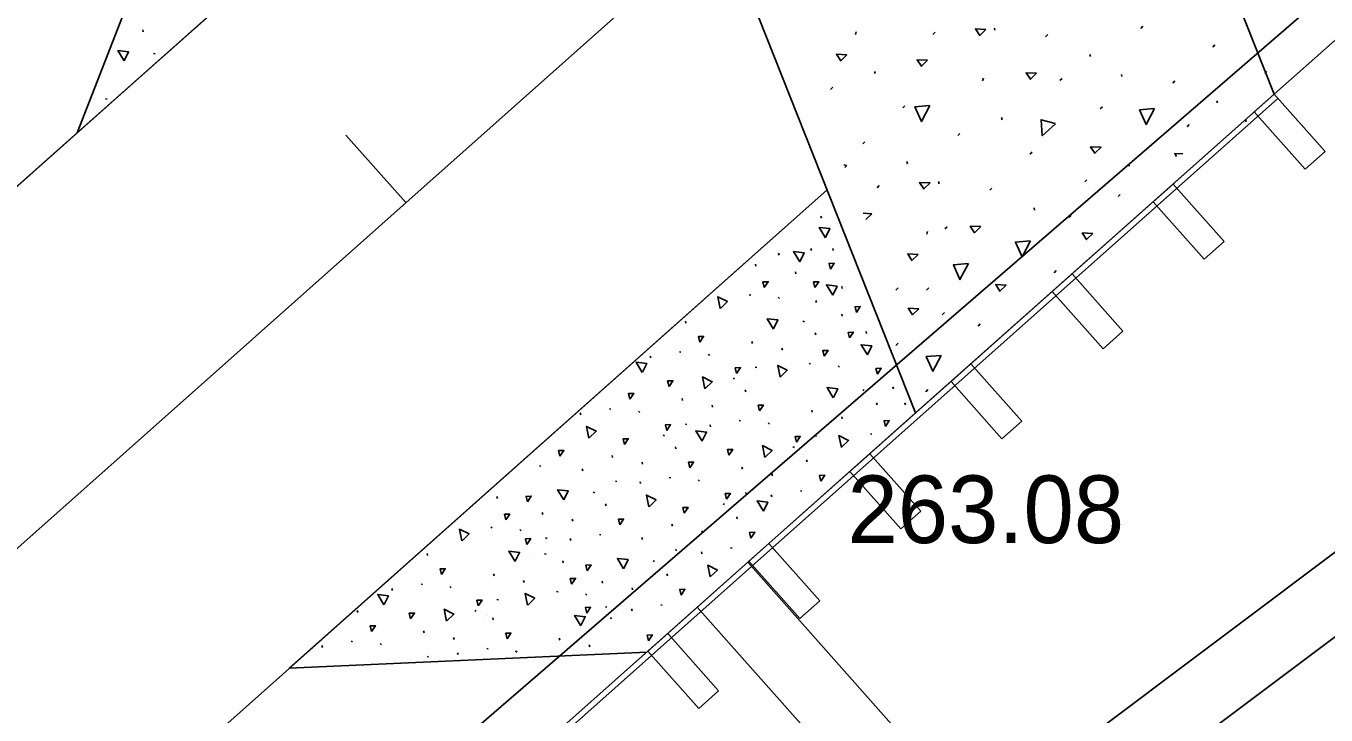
# Model space of a CAD drawing. Extents: x 49683 to 58852, y 49525 to 54803.
# Drawn here: x 55243.3 to 55301, y 53014 to 53044.6 of the extents above; entities that cross this region are included whole.
import ezdxf

# ---------------------------------------------------------------- set-up
doc = ezdxf.new("R2010")
doc.units = 0
for name, color, linetype in [('Level 11', 7, 'Continuous'), ('Level 13', 7, 'Continuous'), ('Level 15', 7, 'Continuous'), ('Level 18', 7, 'Continuous'), ('Level 19', 7, 'Continuous'), ('Level 20', 7, 'Continuous'), ('Level 27', 7, 'Continuous'), ('Level 32', 7, 'Continuous'), ('Level 8', 7, 'Continuous')]:
    doc.layers.add(name, color=color, linetype=linetype)

msp = doc.modelspace()

# ---------------------------------------------------------------- linework, layer by layer
at = {"layer": 'Level 11'}
msp.add_line((55223.521, 52979.087), (55416.975, 53146.156), dxfattribs=at)
at = {"layer": 'Level 13'}
msp.add_line((55279.532, 53069.998), (53969.027, 51905.114), dxfattribs=at)
at = {"layer": 'Level 15'}
for p, q in [((55298.696, 53041.543), (55388.385, 53121.267)), ((55298.696, 53041.543), (55281.433, 53085.069)), ((55282.788, 53027.404), (55265.526, 53070.929)), ((55245.587, 53039.827), (55269.449, 53061.037)), ((55253.595, 53060.324), (55245.587, 53039.827)), ((55286.304, 53044.375), (55286.28, 53044.472)), ((55292.866, 53044.556), (55292.771, 53044.457)), ((55280.123, 53044.188), (55280.153, 53044.31)), ((55283.648, 53044.294), (55283.553, 53044.195)), ((55288.65, 53044.186), (55288.555, 53044.088)), ((55290.541, 53043.209), (55290.517, 53043.306)), ((55296.066, 53043.731), (55295.971, 53043.633)), ((55280.986, 53042.457), (55280.962, 53042.554)), ((55285.761, 53042.136), (55285.791, 53042.258)), ((55289.286, 53042.242), (55289.191, 53042.143)), ((55291.942, 53042.323), (55291.918, 53042.42)), ((55294.288, 53042.134), (55294.193, 53042.035)), ((55298.37, 53042.553), (55298.275, 53042.454)), ((55279.113, 53041.854), (55279.018, 53041.756)), ((55282.788, 53027.404), (55298.696, 53041.543)), ((55282.312, 53041.029), (55282.217, 53040.931)), ((55291.073, 53040.986), (55290.978, 53040.887)), ((55296.179, 53041.156), (55296.156, 53041.254)), ((55286.624, 53040.405), (55286.6, 53040.502)), ((55297.446, 53040.32), (55297.422, 53040.417)), ((55284.751, 53039.802), (55284.656, 53039.704)), ((55294.924, 53040.19), (55294.829, 53040.091)), ((55280.535, 53039.432), (55280.44, 53039.334)), ((55287.95, 53038.977), (55287.855, 53038.879)), ((55282.426, 53038.455), (55282.402, 53038.552)), ((55292.262, 53038.353), (55292.239, 53038.45)), ((55281.171, 53037.488), (55281.076, 53037.389)), ((55283.826, 53037.569), (55283.803, 53037.667)), ((55290.389, 53037.75), (55290.294, 53037.652)), ((55255.003, 53016.086), (55278.865, 53037.296)), ((55286.173, 53037.38), (55286.078, 53037.282)), ((55291.86, 53037.1), (55291.765, 53037.001)), ((55288.064, 53036.403), (55288.04, 53036.5)), ((55289.689, 53036.168), (55289.594, 53036.07)), ((55283.284, 53035.33), (55283.314, 53035.452)), ((55284.182, 53035.664), (55284.087, 53035.565)), ((55289.029, 53033.723), (55288.934, 53033.625)), ((55282.01, 53032.947), (55281.915, 53032.849)), ((55283.367, 53032.947), (55283.272, 53032.849)), ((55284.065, 53031.86), (55283.97, 53031.762)), ((55285.655, 53031.356), (55285.56, 53031.257)), ((55282.01, 53030.502), (55281.915, 53030.404)), ((55283.329, 53028.445), (55283.234, 53028.347)), ((55270.857, 53016.799), (55282.788, 53027.404)), ((55275.342, 53020.785), (55285.8, 53009.019)), ((55273.099, 53018.792), (55283.337, 53007.275)), ((55255.003, 53016.086), (55270.857, 53016.799))]:
    msp.add_line(p, q, dxfattribs=at)
for points in [[(55285.907, 53044.416), (55285.632, 53044.147), (55285.443, 53044.438), (55285.907, 53044.416)], [(55279.74, 53043.294), (55279.465, 53043.025), (55279.276, 53043.316), (55279.74, 53043.294)], [(55283.318, 53043.048), (55283.043, 53042.778), (55282.854, 53043.069), (55283.318, 53043.048)], [(55288.154, 53042.473), (55287.879, 53042.204), (55287.689, 53042.494), (55288.154, 53042.473)], [(55283.423, 53041.038), (55283.048, 53040.33), (55282.757, 53040.982), (55283.409, 53041.038)], [(55293.387, 53040.902), (55293.012, 53040.194), (55292.721, 53040.846), (55293.373, 53040.902)], [(55288.995, 53040.234), (55288.401, 53039.698), (55288.35, 53040.41), (55288.982, 53040.239)], [(55291.017, 53039.19), (55290.742, 53038.921), (55290.552, 53039.212), (55291.017, 53039.19)], [(55294.364, 53038.781), (55294.279, 53038.911), (55294.648, 53038.894)], [(55279.609, 53038.409), (55279.726, 53038.378)], [(55279.739, 53038.373), (55279.654, 53038.297)], [(55283.43, 53037.611), (55283.155, 53037.342), (55282.966, 53037.632), (55283.43, 53037.611)], [(55280.462, 53036.259), (55280.841, 53036.242)], [(55280.841, 53036.242), (55280.573, 53035.979)], [(55285.677, 53035.667), (55285.402, 53035.398), (55285.212, 53035.688), (55285.677, 53035.667)], [(55290.644, 53035.364), (55290.369, 53035.095), (55290.179, 53035.386), (55290.644, 53035.364)], [(55287.881, 53035.035), (55287.507, 53034.327), (55287.215, 53034.98), (55287.868, 53035.035)], [(55282.901, 53034.436), (55282.626, 53034.167), (55282.437, 53034.458), (55282.901, 53034.436)], [(55285.128, 53034.026), (55284.753, 53033.318), (55284.462, 53033.971), (55285.114, 53034.026)], [(55286.805, 53033.075), (55286.53, 53032.806), (55286.34, 53033.096), (55286.805, 53033.075)], [(55282.927, 53032.027), (55282.652, 53031.758), (55282.462, 53032.048), (55282.927, 53032.027)], [(55283.927, 53029.96), (55283.552, 53029.252), (55283.261, 53029.904), (55283.913, 53029.96)]]:
    msp.add_lwpolyline(points, dxfattribs=at)
at = {"layer": 'Level 18'}
for p, q in [((55284.924, 53008.881), (55312.522, 53029.585)), ((55286.724, 53006.481), (55314.322, 53027.185))]:
    msp.add_line(p, q, dxfattribs=at)
at = {"layer": 'Level 19'}
for p, q in [((54181.768, 52078.16), (56150.851, 53828.445)), ((55260.168, 53036.732), (55257.51, 53039.721))]:
    msp.add_line(p, q, dxfattribs=at)
at = {"layer": 'Level 20'}
for p, q in [((54173.795, 52087.129), (55269.449, 53061.037)), ((54189.74, 52069.191), (55278.865, 53037.296))]:
    msp.add_line(p, q, dxfattribs=at)
at = {"layer": 'Level 27'}
for p, q in [((55275.339, 53020.782), (55298.696, 53041.543)), ((55297.812, 53040.758), (55298.696, 53041.543)), ((55298.696, 53041.543), (55300.954, 53039.002)), ((55275.505, 53020.595), (55298.862, 53041.357)), ((55300.07, 53038.217), (55297.812, 53040.758)), ((55300.954, 53039.002), (55300.07, 53038.217)), ((55293.327, 53036.772), (55294.211, 53037.557)), ((55294.211, 53037.557), (55296.469, 53035.016)), ((55295.586, 53034.231), (55293.327, 53036.772)), ((55296.469, 53035.016), (55295.586, 53034.231)), ((55288.843, 53032.786), (55289.727, 53033.571)), ((55289.727, 53033.571), (55291.985, 53031.03)), ((55291.101, 53030.244), (55288.843, 53032.786)), ((55291.985, 53031.03), (55291.101, 53030.244)), ((55284.359, 53028.8), (55285.242, 53029.585)), ((55285.242, 53029.585), (55287.501, 53027.043)), ((55286.617, 53026.258), (55284.359, 53028.8)), ((55287.501, 53027.043), (55286.617, 53026.258)), ((55279.874, 53024.814), (55280.758, 53025.599)), ((55280.758, 53025.599), (55283.016, 53023.057)), ((55282.133, 53022.272), (55279.874, 53024.814)), ((55283.016, 53023.057), (55282.133, 53022.272)), ((55275.39, 53020.827), (55276.273, 53021.613)), ((55276.273, 53021.613), (55278.532, 53019.071)), ((55275.339, 53020.782), (55265.996, 53012.478)), ((55277.648, 53018.286), (55275.39, 53020.827)), ((55275.505, 53020.595), (55266.162, 53012.291)), ((55278.532, 53019.071), (55277.648, 53018.286)), ((55270.905, 53016.841), (55271.789, 53017.626)), ((55271.789, 53017.626), (55274.047, 53015.085)), ((55273.164, 53014.3), (55270.905, 53016.841)), ((55274.047, 53015.085), (55273.164, 53014.3))]:
    msp.add_line(p, q, dxfattribs=at)
at = {"layer": 'Level 8'}
for p, q in [((55248.526, 53044.303), (55248.503, 53044.391)), ((55248.987, 53043.345), (55249.051, 53043.325)), ((55246.855, 53041.336), (55246.918, 53041.315)), ((55278.61, 53036.046), (55278.586, 53036.134)), ((55278.165, 53034.609), (55278.141, 53034.697)), ((55279.136, 53034.609), (55279.112, 53034.697)), ((55275.701, 53033.92), (55275.677, 53034.008)), ((55276.729, 53034.407), (55276.705, 53034.494)), ((55277.477, 53033.577), (55277.453, 53033.665)), ((55279.534, 53032.929), (55279.51, 53033.017)), ((55275.407, 53032.642), (55275.47, 53032.623)), ((55276.692, 53032.545), (55276.752, 53032.487)), ((55278.387, 53032.302), (55278.364, 53032.389)), ((55279.534, 53031.694), (55279.51, 53031.782)), ((55272.601, 53031.393), (55272.577, 53031.481)), ((55277.789, 53031.47), (55277.853, 53031.45)), ((55275.549, 53030.491), (55275.525, 53030.579)), ((55278.356, 53030.874), (55278.332, 53030.962)), ((55280.612, 53030.925), (55280.588, 53031.013)), ((55271.036, 53029.843), (55271.012, 53029.931)), ((55272.306, 53030.115), (55272.37, 53030.095)), ((55273.592, 53030.018), (55273.651, 53029.959)), ((55276.879, 53030.191), (55276.856, 53030.279)), ((55275.674, 53029.442), (55275.738, 53029.422)), ((55278.061, 53029.596), (55278.125, 53029.577)), ((55279.347, 53029.499), (55279.407, 53029.44)), ((55274.689, 53028.943), (55274.752, 53028.923)), ((55275.124, 53028.618), (55275.124, 53028.618)), ((55275.255, 53028.347), (55275.231, 53028.435)), ((55275.253, 53028.724), (55275.253, 53028.724)), ((55280.444, 53028.424), (55280.508, 53028.404)), ((55281.805, 53028.476), (55281.782, 53028.564)), ((55272.448, 53027.964), (55272.425, 53028.052)), ((55273.779, 53027.664), (55273.755, 53027.752)), ((55281.075, 53027.763), (55281.051, 53027.851)), ((55282.331, 53027.768), (55282.307, 53027.855)), ((55267.935, 53027.316), (55267.911, 53027.404)), ((55269.205, 53027.588), (55269.269, 53027.568)), ((55270.491, 53027.491), (55270.551, 53027.432)), ((55274.961, 53027.069), (55275.024, 53027.049)), ((55278.204, 53027.445), (55278.18, 53027.533)), ((55279.534, 53027.145), (55279.51, 53027.233)), ((55272.573, 53026.915), (55272.637, 53026.895)), ((55273.69, 53026.797), (55273.667, 53026.885)), ((55276.246, 53026.972), (55276.306, 53026.913)), ((55280.781, 53026.485), (55280.844, 53026.466)), ((55271.588, 53026.415), (55271.652, 53026.396)), ((55272.023, 53026.091), (55272.023, 53026.091)), ((55272.155, 53025.82), (55272.131, 53025.908)), ((55272.152, 53026.196), (55272.152, 53026.196)), ((55277.343, 53025.897), (55277.407, 53025.877)), ((55278.329, 53026.396), (55278.392, 53026.376)), ((55269.348, 53025.437), (55269.324, 53025.525)), ((55277.778, 53025.572), (55277.778, 53025.572)), ((55277.908, 53025.677), (55277.908, 53025.677)), ((55277.975, 53025.236), (55277.951, 53025.324)), ((55266.105, 53025.061), (55266.169, 53025.041)), ((55268.019, 53024.842), (55267.994, 53024.93)), ((55270.678, 53025.137), (55270.654, 53025.225)), ((55275.103, 53024.918), (55275.079, 53025.006)), ((55269.473, 53024.388), (55269.537, 53024.368)), ((55270.59, 53024.27), (55270.566, 53024.358)), ((55271.86, 53024.542), (55271.924, 53024.522)), ((55273.146, 53024.445), (55273.205, 53024.386)), ((55276.433, 53024.618), (55276.41, 53024.706)), ((55264.241, 53023.616), (55264.217, 53023.704)), ((55268.488, 53023.888), (55268.551, 53023.869)), ((55269.052, 53023.669), (55269.052, 53023.669)), ((55275.228, 53023.869), (55275.292, 53023.849)), ((55276.41, 53023.686), (55276.386, 53023.774)), ((55277.68, 53023.958), (55277.744, 53023.938)), ((55268.923, 53023.564), (55268.923, 53023.564)), ((55269.054, 53023.293), (55269.03, 53023.381)), ((55274.243, 53023.369), (55274.306, 53023.35)), ((55274.678, 53023.045), (55274.678, 53023.045)), ((55274.807, 53023.15), (55274.807, 53023.15)), ((55266.247, 53022.909), (55266.223, 53022.997)), ((55267.578, 53022.609), (55267.554, 53022.697)), ((55272.003, 53022.39), (55271.979, 53022.478)), ((55274.874, 53022.709), (55274.85, 53022.797)), ((55263.946, 53022.337), (55264.01, 53022.318)), ((55265.232, 53022.24), (55265.292, 53022.182)), ((55266.372, 53021.861), (55266.436, 53021.841)), ((55268.76, 53022.015), (55268.823, 53021.995)), ((55270.673, 53021.796), (55270.649, 53021.884)), ((55273.333, 53022.091), (55273.309, 53022.178)), ((55267.489, 53021.743), (55267.465, 53021.831)), ((55272.128, 53021.342), (55272.191, 53021.322)), ((55274.579, 53021.431), (55274.643, 53021.411)), ((55261.14, 53021.088), (55261.116, 53021.176)), ((55265.822, 53021.037), (55265.822, 53021.037)), ((55266.329, 53021.165), (55266.393, 53021.145)), ((55267.154, 53020.764), (55267.131, 53020.852)), ((55271.142, 53020.842), (55271.206, 53020.823)), ((55273.309, 53021.159), (55273.285, 53021.247)), ((55264.089, 53020.186), (55264.065, 53020.274)), ((55271.577, 53020.518), (55271.577, 53020.518)), ((55271.706, 53020.623), (55271.706, 53020.623)), ((55271.774, 53020.182), (55271.75, 53020.27)), ((55259.575, 53019.538), (55259.552, 53019.626)), ((55260.846, 53019.81), (55260.909, 53019.791)), ((55262.131, 53019.713), (55262.191, 53019.654)), ((55265.419, 53019.886), (55265.395, 53019.974)), ((55268.902, 53019.863), (55268.878, 53019.951)), ((55270.232, 53019.563), (55270.209, 53019.651)), ((55264.214, 53019.137), (55264.277, 53019.118)), ((55266.86, 53019.486), (55266.924, 53019.466)), ((55268.145, 53019.389), (55268.205, 53019.33)), ((55258.04, 53018.561), (55258.016, 53018.649)), ((55263.228, 53018.638), (55263.292, 53018.618)), ((55263.793, 53018.419), (55263.793, 53018.419)), ((55269.027, 53018.814), (55269.091, 53018.795)), ((55270.209, 53018.632), (55270.185, 53018.72)), ((55271.479, 53018.904), (55271.543, 53018.884)), ((55263.663, 53018.313), (55263.663, 53018.313)), ((55264.054, 53018.237), (55264.03, 53018.325)), ((55268.477, 53017.991), (55268.477, 53017.991)), ((55269.242, 53018.313), (55269.306, 53018.294)), ((55257.745, 53017.283), (55257.809, 53017.263)), ((55260.988, 53017.659), (55260.964, 53017.747)), ((55262.318, 53017.359), (55262.295, 53017.447)), ((55267.002, 53017.334), (55266.978, 53017.422)), ((55256.475, 53017.011), (55256.451, 53017.099)), ((55259.031, 53017.186), (55259.09, 53017.127)), ((55262.489, 53016.687), (55262.465, 53016.775)), ((55263.759, 53016.958), (55263.823, 53016.939)), ((55265.045, 53016.861), (55265.105, 53016.803)), ((55268.333, 53017.034), (55268.309, 53017.122)), ((55261.113, 53016.61), (55261.177, 53016.59))]:
    msp.add_line(p, q, dxfattribs=at)
for points in [[(55247.677, 53043.014), (55247.404, 53043.473), (55247.876, 53043.413), (55247.682, 53043.022)], [(55278.786, 53035.178), (55278.509, 53035.634), (55278.982, 53035.578), (55278.791, 53035.186)], [(55277.654, 53034.105), (55277.376, 53034.561), (55277.849, 53034.505), (55277.658, 53034.113)], [(55279.006, 53033.786), (55278.946, 53034.036), (55279.177, 53034.045), (55279.006, 53033.786)], [(55276.076, 53032.968), (55276.015, 53033.218), (55276.247, 53033.227), (55276.076, 53032.968)], [(55278.319, 53032.968), (55278.259, 53033.218), (55278.49, 53033.227), (55278.319, 53032.968)], [(55279.11, 53032.627), (55278.833, 53033.083), (55279.306, 53033.028), (55279.114, 53032.635)], [(55274.118, 53032.034), (55274.014, 53032.557), (55274.439, 53032.343), (55274.125, 53032.04)], [(55280.159, 53031.864), (55280.099, 53032.113), (55280.33, 53032.122), (55280.159, 53031.864)], [(55276.482, 53031.128), (55276.205, 53031.584), (55276.678, 53031.528), (55276.486, 53031.136)], [(55273.211, 53030.542), (55273.151, 53030.792), (55273.382, 53030.801), (55273.211, 53030.542)], [(55279.856, 53030.73), (55279.796, 53030.979), (55280.027, 53030.989), (55279.856, 53030.73)], [(55278.73, 53029.922), (55278.67, 53030.172), (55278.901, 53030.181), (55278.73, 53029.922)], [(55280.647, 53029.976), (55280.37, 53030.432), (55280.843, 53030.376), (55280.652, 53029.984)], [(55270.661, 53029.205), (55270.384, 53029.661), (55270.857, 53029.605), (55270.666, 53029.213)], [(55274.848, 53029.155), (55274.787, 53029.405), (55275.019, 53029.414), (55274.848, 53029.155)], [(55276.773, 53028.988), (55276.669, 53029.511), (55277.094, 53029.297), (55276.78, 53028.993)], [(55281.09, 53029.131), (55281.029, 53029.38), (55281.261, 53029.39), (55281.09, 53029.131)], [(55271.848, 53028.578), (55271.787, 53028.828), (55272.019, 53028.837), (55271.848, 53028.578)], [(55273.444, 53028.481), (55273.34, 53029.005), (55273.765, 53028.791), (55273.452, 53028.487)], [(55270.11, 53028.015), (55270.05, 53028.264), (55270.281, 53028.274), (55270.11, 53028.015)], [(55279.136, 53028.082), (55278.859, 53028.538), (55279.332, 53028.482), (55279.141, 53028.09)], [(55275.865, 53027.496), (55275.805, 53027.746), (55276.036, 53027.755), (55275.865, 53027.496)], [(55281.45, 53026.811), (55281.389, 53027.061), (55281.621, 53027.07), (55281.45, 53026.811)], [(55268.298, 53026.289), (55268.194, 53026.812), (55268.619, 53026.598), (55268.305, 53026.295)], [(55271.747, 53026.628), (55271.687, 53026.878), (55271.918, 53026.887), (55271.747, 53026.628)], [(55273.316, 53026.159), (55273.039, 53026.615), (55273.512, 53026.559), (55273.321, 53026.167)], [(55269.867, 53026.006), (55269.807, 53026.255), (55270.038, 53026.265), (55269.867, 53026.006)], [(55276.099, 53025.435), (55275.995, 53025.959), (55276.42, 53025.744), (55276.106, 53025.441)], [(55277.502, 53026.109), (55277.442, 53026.359), (55277.673, 53026.368), (55277.502, 53026.109)], [(55279.492, 53025.877), (55279.388, 53026.4), (55279.813, 53026.186), (55279.499, 53025.883)], [(55267.01, 53025.488), (55266.95, 53025.737), (55267.181, 53025.747), (55267.01, 53025.488)], [(55274.502, 53025.532), (55274.442, 53025.781), (55274.673, 53025.791), (55274.502, 53025.532)], [(55272.765, 53024.969), (55272.705, 53025.218), (55272.936, 53025.228), (55272.765, 53024.969)], [(55278.585, 53024.385), (55278.525, 53024.635), (55278.756, 53024.644), (55278.585, 53024.385)], [(55265.565, 53023.457), (55265.505, 53023.706), (55265.736, 53023.716), (55265.565, 53023.457)], [(55267.18, 53023.546), (55266.903, 53024.002), (55267.376, 53023.946), (55267.185, 53023.554)], [(55270.953, 53023.243), (55270.848, 53023.766), (55271.274, 53023.552), (55270.96, 53023.249)], [(55274.402, 53023.582), (55274.342, 53023.831), (55274.573, 53023.841), (55274.402, 53023.582)], [(55272.522, 53022.96), (55272.462, 53023.209), (55272.693, 53023.219), (55272.522, 53022.96)], [(55276.035, 53023.048), (55275.758, 53023.504), (55276.231, 53023.448), (55276.04, 53023.056)], [(55264.615, 53022.663), (55264.555, 53022.913), (55264.786, 53022.922), (55264.615, 53022.663)], [(55269.664, 53022.442), (55269.604, 53022.691), (55269.835, 53022.7), (55269.664, 53022.442)], [(55262.658, 53021.729), (55262.554, 53022.252), (55262.979, 53022.038), (55262.665, 53021.735)], [(55275.484, 53021.858), (55275.424, 53022.107), (55275.655, 53022.117), (55275.484, 53021.858)], [(55265.021, 53020.823), (55264.744, 53021.279), (55265.217, 53021.223), (55265.026, 53020.831)], [(55265.546, 53021.574), (55265.486, 53021.823), (55265.717, 53021.833), (55265.546, 53021.574)], [(55269.835, 53020.5), (55269.558, 53020.956), (55270.031, 53020.9), (55269.84, 53020.508)], [(55261.75, 53020.237), (55261.69, 53020.487), (55261.921, 53020.496), (55261.75, 53020.237)], [(55268.219, 53020.411), (55268.159, 53020.66), (55268.39, 53020.67), (55268.219, 53020.411)], [(55273.672, 53020.132), (55273.568, 53020.655), (55273.993, 53020.441), (55273.679, 53020.138)], [(55267.529, 53019.812), (55267.469, 53020.061), (55267.7, 53020.07), (55267.529, 53019.812)], [(55272.384, 53019.331), (55272.324, 53019.58), (55272.555, 53019.59), (55272.384, 53019.331)], [(55259.201, 53018.9), (55258.924, 53019.356), (55259.397, 53019.3), (55259.206, 53018.908)], [(55263.387, 53018.85), (55263.327, 53019.1), (55263.558, 53019.109), (55263.387, 53018.85)], [(55265.572, 53018.877), (55265.467, 53019.401), (55265.892, 53019.186), (55265.579, 53018.883)], [(55260.387, 53018.273), (55260.327, 53018.523), (55260.558, 53018.532), (55260.387, 53018.273)], [(55261.984, 53018.177), (55261.88, 53018.7), (55262.305, 53018.486), (55261.991, 53018.182)], [(55267.935, 53017.971), (55267.658, 53018.427), (55268.131, 53018.371), (55267.94, 53017.979)], [(55268.201, 53018.528), (55268.141, 53018.777), (55268.372, 53018.786), (55268.201, 53018.528)], [(55258.65, 53017.71), (55258.59, 53017.96), (55258.821, 53017.969), (55258.65, 53017.71)], [(55264.664, 53017.386), (55264.604, 53017.635), (55264.835, 53017.644), (55264.664, 53017.386)], [(55270.939, 53017.3), (55270.879, 53017.549), (55271.11, 53017.559), (55270.939, 53017.3)]]:
    msp.add_lwpolyline(points, dxfattribs=at)

# ---------------------------------------------------------------- texts
at = {"layer": 'Level 32'}
msp.add_text('263.08', height=3, dxfattribs=at).set_placement((55279.766, 53021.634))

doc.saveas('drawing.dxf')
